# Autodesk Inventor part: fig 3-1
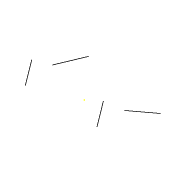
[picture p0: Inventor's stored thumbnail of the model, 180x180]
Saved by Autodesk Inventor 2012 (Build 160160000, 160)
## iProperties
Created: 2011-07
Part Number: fig 3-1
Material: Default
Document SubType Name: Modeling
Designer: CadCim
Density: 1 g/cm^3
Author: CadCim
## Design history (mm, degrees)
sketch "Sketch1"
  geometry: L1 (-29, 4)-(-20, -8); L2 (-22, 7)-(-17, 19); L3 (5, 4)-(14, -8); L4 (13.764, 5.293)-(23.529, 12.617); 1 further point
  constraints: 8 end point, 1 perpendicular, 1 other
